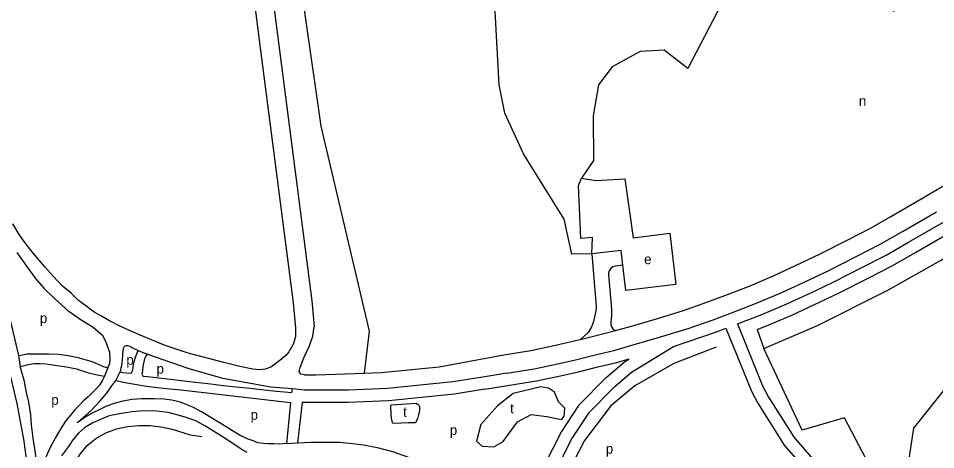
# Model space of a CAD drawing. Extents: x 154320 to 156262, y 382651 to 384180.
# Drawn here: x 155184.2 to 155553.7, y 383472.2 to 383646 of the extents above; entities that cross this region are included whole.
import ezdxf

# ---------------------------------------------------------------- set-up
doc = ezdxf.new("R2010")
doc.units = 0
for name, color, linetype in [('BLT_Basislijn', 7, 'Continuous'), ('BLT_Centroide', 7, 'Continuous'), ('BLT_Vlakafsluiter', 7, 'Continuous')]:
    doc.layers.add(name, color=color, linetype=linetype)

msp = doc.modelspace()

# ---------------------------------------------------------------- linework, layer by layer
at = {"layer": 'BLT_Basislijn'}
for p, q in [((155535.63, 383566.14), (155549, 383573.88)), ((155427.03, 383552.5), (155415.14, 383551.07)), ((155427.72, 383546.57), (155427.03, 383552.5)), ((155410.64, 383516.63), (155424.79, 383520.24)), ((155424.79, 383520.24), (155427.17, 383520.84)), ((155409.1, 383516.24), (155410.64, 383516.63)), ((155232.52, 383512.12), (155236.06, 383510.72)), ((155184.25, 383510.12), (155184.97, 383505.66)), ((155220.33, 383505.18), (155218.87, 383501.76)), ((155223.47, 383500.11), (155225.25, 383503.48)), ((155299.33, 383496.16), (155294.59, 383496.74)), ((155292.2, 383474.59), (155296.71, 383474.89))]:
    msp.add_line(p, q, dxfattribs=at)
for points in [[(155415.14, 383551.07), (155407.08, 383550.96), (155404.08, 383565.06), (155387.7, 383591.41), (155380.21, 383607.78), (155377.91, 383619.19), (155376.03, 383653.96), (155394.55, 383659.78), (155392.73, 383684.28), (155384.13, 383700.15), (155363.76, 383731.77), (155336.24, 383809.42), (155323.11, 383849.23), (155303.53, 383922.25), (155300.42, 383947.66), (155300.92, 383955.47), (155295.18, 383988.01), (155291.91, 384000.91)], [(155250.11, 383982.53), (155261.74, 383912.14), (155306.1, 383602.51), (155325.55, 383519.95), (155323.53, 383503)], [(155240.24, 383952.8), (155244.25, 383922.67), (155254.52, 383841.16), (155269.64, 383728.11), (155281.68, 383634.19), (155294.91, 383531.3), (155295.85, 383521.14)], [(155247.67, 383953.79), (155251.69, 383923.64), (155261.96, 383842.13), (155277.07, 383729.08), (155289.12, 383635.15), (155302.36, 383532.12), (155303.32, 383521.83)], [(155634.56, 383646.03), (155632.06, 383646.95), (155621.94, 383663.64), (155608.88, 383712.13), (155584.78, 383742.91), (155588.99, 383764.63), (155578.77, 383762.24), (155550.55, 383734.97), (155547.89, 383720.5), (155553.04, 383704.86), (155548.1, 383677.23), (155536.76, 383648.78), (155496.98, 383683.49), (155480.24, 383672.06), (155468.97, 383655.07), (155453.89, 383625.83), (155444.31, 383633.22), (155434.65, 383632.62), (155423.38, 383626.53), (155417.9, 383619.16), (155415.76, 383606.74), (155415.92, 383588.66), (155411.04, 383581.59)], [(155473.87, 383522.91), (155483.71, 383526.69), (155493.7, 383530.96), (155504.83, 383536.09), (155512.64, 383539.82), (155524.25, 383545.7), (155533.73, 383550.62), (155542.77, 383555.83), (155556.5, 383563.77), (155564.94, 383568.79), (155575.66, 383575.68), (155583.25, 383580.77), (155590.73, 383586.39), (155597.25, 383591.37), (155605.88, 383598.5), (155612.82, 383604.92), (155620.6, 383612.55), (155627.28, 383619.42), (155632.9, 383625.15), (155641.67, 383634.9), (155649.57, 383644.77), (155656.1, 383653.43)], [(155549, 383573.88), (155550.17, 383574.56), (155558.37, 383579.42), (155568.8, 383586.13), (155576, 383590.96), (155583.18, 383596.36), (155589.47, 383601.17), (155597.65, 383607.92), (155604.2, 383613.97), (155611.74, 383621.37), (155618.33, 383628.15), (155623.79, 383633.72), (155632.13, 383642.99), (155634.56, 383646.03)], [(155481.78, 383520.59), (155485.59, 383522.05), (155495.73, 383526.39), (155506.95, 383531.57), (155514.85, 383535.33), (155526.53, 383541.25), (155536.13, 383546.23), (155545.27, 383551.5), (155559.03, 383559.46), (155567.57, 383564.53), (155578.41, 383571.5), (155586.14, 383576.69), (155593.74, 383582.41), (155600.36, 383587.46), (155609.17, 383594.73), (155616.27, 383601.3), (155624.15, 383609.02), (155630.85, 383615.93), (155636.55, 383621.73), (155645.33, 383631.5)], [(155484.43, 383512.94), (155506.14, 383522.26), (155534.38, 383536.42), (155555.63, 383548.36), (155578.72, 383562.32), (155598.15, 383576.38), (155611.08, 383587.01), (155630.5, 383606.01), (155641.48, 383618.06), (155645.65, 383618.9)], [(155415.14, 383551.07), (155415.52, 383557.63), (155410.7, 383557.28), (155409.84, 383578.69), (155411.04, 383581.59)], [(155411.04, 383581.59), (155416.83, 383580.6), (155428.44, 383581.38), (155431.82, 383557.51), (155446.6, 383559.37), (155449.04, 383538.75), (155428.92, 383536.35), (155427.72, 383546.57)], [(155380.92, 383502.97), (155392.03, 383504.8), (155400.89, 383506.68), (155408.68, 383508.4), (155416.47, 383510.36), (155424, 383512.13), (155432.26, 383514.51), (155442.42, 383517.48), (155453.97, 383521.06), (155464.06, 383524.5), (155472.49, 383527.74), (155481.83, 383531.32), (155491.66, 383535.53), (155502.71, 383540.62), (155510.44, 383544.31), (155521.97, 383550.15), (155531.32, 383555), (155540.27, 383560.16), (155553.97, 383568.09)], [(155427.17, 383520.84), (155430.17, 383521.71), (155440.26, 383524.66), (155451.65, 383528.19), (155461.51, 383531.56), (155469.81, 383534.74), (155479.01, 383538.27), (155488.62, 383542.38), (155499.52, 383547.41), (155507.13, 383551.04), (155518.54, 383556.82), (155527.72, 383561.58), (155535.63, 383566.14)], [(155295.85, 383521.14), (155295.85, 383517.83), (155295.03, 383515), (155294.07, 383513.25), (155293.6, 383512.37), (155293.13, 383511.63), (155291.96, 383510.15), (155289.59, 383508.15), (155287.94, 383506.85), (155285.93, 383505.43), (155283.57, 383504.6), (155281.33, 383504.37), (155278.61, 383504.6), (155273.42, 383505.66), (155266.92, 383507.32), (155252.63, 383511.1), (155243.42, 383514.17), (155233.27, 383518.3), (155225.12, 383521.97), (155220.87, 383524.09), (155217.68, 383525.98), (155214.73, 383527.64), (155211.42, 383530.12), (155208.47, 383532.24), (155205.64, 383535.08), (155201.98, 383538.03), (155198.31, 383542.05), (155194.89, 383545.83), (155190.28, 383551.26), (155187.21, 383555.16), (155184.62, 383558.94), (155182.02, 383563.2)], [(155183.55, 383551.62), (155187.45, 383546.07), (155191.11, 383541.22), (155194.54, 383537.32), (155198.79, 383533.15)], [(155415.14, 383551.07), (155416.93, 383529.91), (155416.85, 383528.1), (155415.93, 383523.82), (155415.1, 383521.68), (155413.7, 383519.44), (155410.64, 383516.63)], [(155427.72, 383546.57), (155424.65, 383546.15), (155423.65, 383545.83), (155422.8, 383545.21), (155422.12, 383544.27), (155421.87, 383543.35), (155421.87, 383542.62), (155422.92, 383530.38), (155423.08, 383528.3), (155423.13, 383526.13), (155422.82, 383523.75), (155422.85, 383522.63), (155423.13, 383521.71), (155423.7, 383520.93), (155424.48, 383520.34), (155424.79, 383520.24)], [(155698.05, 383531.88), (155690.89, 383537.69), (155681.93, 383540.29), (155671.11, 383539.57), (155664.57, 383538.95), (155596.99, 383507.93), (155581.65, 383515.6), (155558.93, 383498.71), (155544.8, 383480.89), (155542.65, 383466.76)], [(155220.33, 383505.18), (155221.1, 383506.96), (155221.22, 383508.98), (155221.09, 383511.27), (155219.41, 383515.8), (155218.21, 383518.01), (155214.3, 383521.44), (155211.22, 383523.34), (155209.06, 383524.62), (155204.6, 383527.85), (155198.79, 383533.15)], [(155180.44, 383526.65), (155184.25, 383510.12)], [(155473.87, 383522.91), (155483.98, 383497.86), (155486.36, 383493.38), (155496.62, 383477.01), (155506.99, 383465.16), (155518.91, 383453.74), (155544.48, 383433.68), (155554.14, 383425.4), (155573.89, 383407.44), (155578.88, 383402.26), (155583.05, 383396.74)], [(155299.45, 383502.3), (155298.03, 383502.6), (155297.38, 383503.65), (155297.68, 383505.26), (155299.23, 383509.22), (155301.53, 383514.08), (155302.79, 383517.88), (155303.32, 383521.83)], [(155448.12, 383513.77), (155465.77, 383519.8), (155469.2, 383521.12)], [(155469.2, 383521.12), (155479.44, 383495.74), (155482.03, 383490.88), (155492.59, 383474.01), (155501.8, 383463.51)], [(155379.7, 383510.37), (155390.64, 383512.18), (155399.31, 383514.01), (155406.96, 383515.7), (155409.1, 383516.24)], [(155232.52, 383512.12), (155230.46, 383512.93), (155229.62, 383513.43), (155228.88, 383513.85), (155228.35, 383514), (155227.91, 383514), (155227.53, 383513.97), (155227.14, 383513.88), (155226.82, 383513.61), (155226.67, 383513.43), (155226.52, 383513.2), (155226.43, 383512.9), (155226.2, 383510.6), (155226.17, 383510.24), (155226.17, 383509.8), (155225.75, 383505.81), (155225.55, 383505.14), (155225.25, 383503.48)], [(155225.25, 383503.48), (155226.35, 383503.28), (155229.39, 383502.95), (155229.74, 383503.19), (155230.12, 383503.66), (155230.33, 383504.37), (155230.45, 383505.4), (155230.57, 383506.35), (155230.86, 383507.76), (155231.45, 383509.48), (155232.52, 383512.12)], [(155465.31, 383513.49), (155448.18, 383506.86), (155432.53, 383497.96), (155422.89, 383489.79), (155412.29, 383475.83), (155404.43, 383460.88), (155400.38, 383446.77), (155398.74, 383432.48)], [(155424.44, 383497.62), (155431.14, 383503.4), (155448.12, 383513.77)], [(155542.65, 383466.76), (155530.01, 383460.09), (155516.89, 383484.95), (155499.97, 383479.97), (155484.43, 383512.94)], [(155184.25, 383510.12), (155185.98, 383510.42), (155187.64, 383510.84), (155196.53, 383510.84), (155200.49, 383510.62), (155204.35, 383510.19), (155208.26, 383509.34), (155210.44, 383508.64), (155212.06, 383508.26), (155214.19, 383507.54), (155217.28, 383506.21), (155218.38, 383505.67), (155220.33, 383505.18)], [(155236.06, 383510.72), (155235.56, 383509.89), (155235.02, 383508.8), (155234.61, 383507.06), (155234.37, 383505.67), (155234.17, 383504.13), (155234.05, 383503.01), (155233.99, 383502.6), (155234.05, 383502.27), (155234.2, 383502.04), (155234.61, 383501.86), (155236.23, 383501.71), (155248.84, 383500.15), (155255.48, 383499.38), (155260.5, 383498.85), (155266.79, 383498.08), (155271.84, 383497.46), (155277.62, 383496.93), (155283.17, 383496.31), (155288.22, 383495.69), (155294.35, 383495.16)], [(155294.59, 383496.74), (155285.96, 383497.34), (155266.59, 383500.88), (155252.66, 383504.9), (155239.44, 383509.39), (155236.06, 383510.72)], [(155323.53, 383503), (155330.36, 383503.24), (155353.74, 383505.61), (155379.7, 383510.37)], [(155372.1, 383496.49), (155392.95, 383499.89), (155401.95, 383501.79), (155409.83, 383503.53), (155417.65, 383505.5), (155425.26, 383507.29), (155430.28, 383508.73)], [(155421.03, 383501.28), (155428.19, 383507.45), (155430.28, 383508.73)], [(155180.25, 383504.95), (155183.56, 383490.78), (155186.39, 383475.66), (155187.57, 383467.39), (155187.93, 383460.65)], [(155184.97, 383505.66), (155188.16, 383506.49), (155190.64, 383506.84), (155193, 383506.84), (155195.25, 383506.73), (155197.96, 383506.37), (155200.8, 383506.02), (155203.63, 383505.54), (155207.65, 383504.72), (155212.49, 383503.18), (155215.91, 383502.35), (155218.87, 383501.76)], [(155192.18, 383460.54), (155191.71, 383465.5), (155191.11, 383470.81), (155190.17, 383476.84), (155189.58, 383482.15), (155189.23, 383486.17), (155188.4, 383491.25), (155187.57, 383495.15), (155186.51, 383500.23), (155184.97, 383505.66)], [(155218.87, 383501.76), (155218.04, 383499.87), (155216.86, 383498.22), (155215.56, 383496.68), (155214.02, 383495.03), (155212.37, 383493.49), (155210.36, 383491.72), (155208.59, 383489.83), (155206.82, 383488.06), (155205.17, 383486.05), (155203.51, 383484.04), (155201.98, 383481.8), (155200.44, 383479.08), (155199.03, 383476.84), (155197.02, 383473.06), (155195.25, 383469.16), (155193.71, 383465.61), (155192.18, 383460.54)], [(155371.31, 383501.42), (155359.17, 383499.46), (155332.96, 383496.87), (155317.13, 383496.16), (155299.33, 383496.16)], [(155299.45, 383502.3), (155304.14, 383502.3), (155323.53, 383503)], [(155380.92, 383502.97), (155371.31, 383501.42)], [(155421.03, 383501.28), (155409.88, 383490.01), (155402.96, 383479.51), (155395.61, 383464.95), (155391.76, 383452.59), (155389.49, 383433.02), (155383.15, 383430.57)], [(155207.88, 383482.98), (155213.67, 383488.06), (155217.09, 383491.72), (155219.81, 383494.91), (155221.94, 383497.87), (155223.47, 383500.11)], [(155223.47, 383500.11), (155227.25, 383499.28), (155231.15, 383498.57), (155235.87, 383497.75), (155240.12, 383497.27), (155245.2, 383496.68), (155249.69, 383496.33), (155293.85, 383491.14)], [(155424.44, 383497.62), (155413.79, 383486.85), (155407.29, 383476.99), (155400.26, 383463.07), (155396.67, 383451.55), (155394.33, 383431.37)], [(155294.35, 383495.16), (155294.59, 383496.74)], [(155372.1, 383496.49), (155359.82, 383494.5), (155333.31, 383491.88), (155317.25, 383491.16), (155298.59, 383491.16)], [(155257.95, 383487.47), (155254.53, 383489.24), (155251.81, 383490.42), (155249.57, 383491.25), (155246.03, 383492.08), (155242.96, 383492.55), (155239.06, 383492.67), (155233.86, 383492.67), (155230.08, 383492.43), (155226.3, 383491.72), (155223.23, 383490.9), (155219.69, 383489.71), (155217.09, 383488.41), (155213.91, 383486.88), (155211.43, 383485.46), (155207.88, 383482.98)], [(155293.85, 383491.14), (155292.2, 383474.59)], [(155298.59, 383491.16), (155296.71, 383474.89)], [(155276.4, 383470.99), (155273.92, 383472.41), (155271.44, 383474.06), (155267.07, 383476.9), (155259.63, 383481.62), (155255.74, 383483.75), (155251.84, 383485.17), (155248.53, 383486.11), (155244.52, 383487.17), (155239.8, 383487.65), (155234.6, 383487.77), (155230.11, 383487.41), (155224.92, 383486.58), (155220.78, 383485.76), (155217.36, 383484.34), (155214.29, 383483.04), (155210.86, 383480.91), (155208.5, 383478.79), (155206.14, 383476.19), (155204.37, 383473.47), (155201.65, 383469.69)], [(155292.2, 383474.59), (155289.36, 383474.36), (155287.12, 383474.47), (155284.88, 383474.47), (155282.87, 383474.59), (155280.74, 383474.95), (155278.74, 383475.77), (155276.85, 383476.37), (155275.31, 383477.07), (155273.78, 383477.78), (155272.24, 383478.73), (155270.47, 383479.79), (155268.58, 383480.97), (155257.95, 383487.47)], [(155202.12, 383454.55), (155203.22, 383458.05), (155204.71, 383462.35), (155206.67, 383466.46), (155209.07, 383470.32), (155212, 383473.81), (155215.49, 383476.72), (155219.45, 383478.96), (155223.73, 383480.5), (155228.19, 383481.44), (155232.72, 383481.87), (155237.27, 383481.91), (155241.78, 383481.33), (155246.23, 383480.38), (155253.43, 383478.2), (155258.13, 383477.52)], [(155296.71, 383474.89), (155302.03, 383475.13), (155307.58, 383475.24), (155313.6, 383475.13), (155318.8, 383474.65), (155323.28, 383474.06), (155328.72, 383473), (155334.86, 383471.46), (155341, 383469.34), (155345.49, 383467.45), (155350.56, 383465.08), (155354.46, 383462.96), (155358.59, 383460.36), (155362.02, 383458.11), (155365.8, 383455.28), (155369.69, 383451.73), (155372.53, 383448.78), (155375.36, 383445.12), (155378.67, 383440.28), (155380.56, 383436.61), (155382.45, 383432.36), (155383.15, 383430.57)]]:
    msp.add_lwpolyline(points, dxfattribs=at)
for points in [[(155400.13, 383495.33), (155397.78, 383496.98), (155394.6, 383497.54), (155383.57, 383494.75), (155377.15, 383489.78), (155370.43, 383482.32), (155368.81, 383475.66), (155370.99, 383473.59), (155375.75, 383473.34), (155379.5, 383475.43), (155381.29, 383477.93), (155385.22, 383483.43), (155390.77, 383486.4), (155397.07, 383485.52), (155402.94, 383484.26), (155404.01, 383485.73), (155404.33, 383488.9), (155401.83, 383491.44)], [(155334.27, 383490), (155334.49, 383490.29), (155344.39, 383490.92), (155345.15, 383490.46), (155345.49, 383490.14), (155345.63, 383489.83), (155345.72, 383489.39), (155345.77, 383488.72), (155345.74, 383487.96), (155345.62, 383487.13), (155345.43, 383486.28), (155344.93, 383484.67), (155344.3, 383483.22), (155344.13, 383482.93), (155341.28, 383483.04), (155335.87, 383482.7), (155334.97, 383482.8), (155334.88, 383483.06), (155334.55, 383484.82), (155334.44, 383486.04)]]:
    msp.add_lwpolyline(points, close=True, dxfattribs=at)
at = {"layer": 'BLT_Vlakafsluiter'}
msp.add_line((155481.78, 383520.59), (155484.43, 383512.94), dxfattribs=at)

# ---------------------------------------------------------------- texts
at = {"layer": 'BLT_Centroide'}
msp.add_text('n', height=4, rotation=359.5, dxfattribs=at).set_placement((155522.73, 383610.75))
for s, p in [('e', (155436.27, 383546.95)), ('p', (155192.9, 383523.18)), ('p', (155227.72, 383506.39)), ('p', (155239.9, 383502.8)), ('p', (155197.5, 383490.26)), ('t', (155382.29, 383486.8)), ('p', (155277.77, 383484.23)), ('t', (155339.19, 383485.41)), ('p', (155358, 383478.1)), ('p', (155420.81, 383470.57))]:
    msp.add_text(s, height=4, dxfattribs=at).set_placement(p)

doc.saveas('drawing.dxf')
